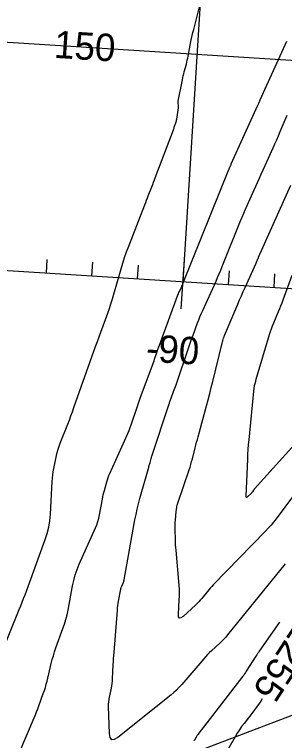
# Model space of a CAD drawing. Extents: x 658976 to 668721, y 639543 to 647196.
# Drawn here: x 661883.9 to 661943.1, y 641733.2 to 641892.5 of the extents above; entities that cross this region are included whole.
import ezdxf

# ---------------------------------------------------------------- set-up
doc = ezdxf.new("R2010")
doc.units = 0
for name, color, linetype in [('Ex_Contour Labels', 7, 'Continuous'), ('Ex_Major Contours', 7, 'Continuous'), ('Ex_Minor Contours', 7, 'Continuous'), ('R_Axis', 7, 'Continuous'), ('R_Axis Annot', 7, 'Continuous'), ('R_Grid', 7, 'Continuous'), ('R_Water', 7, 'Continuous')]:
    doc.layers.add(name, color=color, linetype=linetype)

msp = doc.modelspace()

# ---------------------------------------------------------------- linework, layer by layer
at = {"layer": 'Ex_Major Contours'}
for points in [[(661880.35, 641750.68), (661884.95, 641761.94), (661885.28, 641762.74), (661885.6, 641763.55), (661885.9, 641764.36), (661886.21, 641765.17), (661890.65, 641777.29), (661891.09, 641778.66), (661891.43, 641780.04), (661891.66, 641781.44), (661891.79, 641782.87), (661892.18, 641790.04), (661892.23, 641790.76), (661892.31, 641791.47), (661892.41, 641792.18), (661892.54, 641792.89), (661893.11, 641795.72), (661893.27, 641796.43), (661893.46, 641797.12), (661893.68, 641797.81), (661893.93, 641798.48), (661895.56, 641802.6), (661895.92, 641803.51), (661896.27, 641804.43), (661896.61, 641805.34), (661896.94, 641806.26), (661901.32, 641818.63), (661901.69, 641819.67), (661902.07, 641820.72), (661902.44, 641821.76), (661902.82, 641822.8), (661904.33, 641826.96), (661904.7, 641828), (661905.05, 641829.05), (661905.38, 641830.1), (661905.69, 641831.17), (661907.25, 641836.67), (661907.63, 641837.94), (661908.03, 641839.19), (661908.47, 641840.44), (661908.93, 641841.68), (661912.46, 641850.77), (661912.65, 641851.26), (661912.84, 641851.75), (661913.03, 641852.25), (661913.23, 641852.74), (661914, 641854.71), (661914.19, 641855.2), (661914.38, 641855.69), (661914.57, 641856.19), (661914.76, 641856.68), (661918.72, 641867.2), (661918.79, 641867.39), (661918.86, 641867.58), (661918.93, 641867.78), (661919, 641867.97), (661919.27, 641868.74), (661919.33, 641868.94), (661919.38, 641869.13), (661919.43, 641869.33), (661919.46, 641869.53), (661919.83, 641872.02), (661919.85, 641872.14), (661919.85, 641872.26), (661919.85, 641872.39), (661919.84, 641872.51), (661919.78, 641872.99), (661919.77, 641873.11), (661919.76, 641873.23), (661919.77, 641873.35), (661919.79, 641873.47), (661920.7, 641878.13), (661920.79, 641878.57), (661920.89, 641879.01), (661921, 641879.45), (661921.11, 641879.89), (661921.57, 641881.63), (661921.68, 641882.06), (661921.78, 641882.5), (661921.88, 641882.94), (661921.97, 641883.38), (661922.57, 641886.54), (661922.71, 641887.21), (661922.85, 641887.88), (661923, 641888.55), (661923.17, 641889.22), (661924.65, 641895.06)], [(661938.21, 641742.37), (661937.88, 641741.86), (661937.38, 641741.13), (661936.87, 641740.43), (661936.34, 641739.73), (661934.21, 641736.95), (661933.68, 641736.25), (661933.19, 641735.53), (661932.72, 641734.8), (661932.27, 641734.05), (661929.5, 641729.16)]]:
    msp.add_lwpolyline(points, dxfattribs=at)
at = {"layer": 'Ex_Minor Contours'}
for points in [[(661885.05, 641730.78), (661888.21, 641738.16), (661888.48, 641738.81), (661888.75, 641739.48), (661889.01, 641740.15), (661889.25, 641740.82), (661890.22, 641743.51), (661890.45, 641744.19), (661890.66, 641744.87), (661890.86, 641745.56), (661891.04, 641746.25), (661891.96, 641750.09), (661892.18, 641750.96), (661892.43, 641751.82), (661892.7, 641752.67), (661892.99, 641753.52), (661894.53, 641757.75), (661894.87, 641758.74), (661895.17, 641759.74), (661895.42, 641760.76), (661895.63, 641761.79), (661896.6, 641767.12), (661896.87, 641768.35), (661897.2, 641769.55), (661897.6, 641770.73), (661898.08, 641771.88), (661901.66, 641779.87), (661901.94, 641780.56), (661902.18, 641781.26), (661902.38, 641781.98), (661902.53, 641782.71), (661903.16, 641786.16), (661903.26, 641786.64), (661903.36, 641787.12), (661903.47, 641787.59), (661903.6, 641788.06), (661904.13, 641789.95), (661904.27, 641790.42), (661904.42, 641790.88), (661904.6, 641791.33), (661904.79, 641791.78), (661908.73, 641800.59), (661909, 641801.22), (661909.25, 641801.85), (661909.49, 641802.49), (661909.71, 641803.13), (661910.57, 641805.71), (661910.79, 641806.36), (661911.01, 641807), (661911.24, 641807.65), (661911.47, 641808.29), (661914.35, 641816.15), (661914.49, 641816.53), (661914.62, 641816.91), (661914.76, 641817.29), (661914.89, 641817.67), (661915.41, 641819.2), (661915.54, 641819.58), (661915.67, 641819.96), (661915.8, 641820.34), (661915.94, 641820.72), (661919.64, 641830.75), (661919.73, 641830.99), (661919.83, 641831.23), (661919.93, 641831.47), (661920.04, 641831.71), (661920.47, 641832.66), (661920.57, 641832.9), (661920.68, 641833.14), (661920.78, 641833.38), (661920.88, 641833.62), (661930.87, 641858.48), (661930.92, 641858.58), (661930.96, 641858.69), (661931, 641858.79), (661931.05, 641858.89), (661931.23, 641859.3), (661931.28, 641859.4), (661931.32, 641859.5), (661931.37, 641859.6), (661931.41, 641859.71), (661937.27, 641872.63), (661937.32, 641872.72), (661937.36, 641872.82), (661937.4, 641872.92), (661937.44, 641873.02), (661937.61, 641873.41), (661937.65, 641873.51), (661937.7, 641873.61), (661937.74, 641873.71), (661937.78, 641873.8), (661943.62, 641886.68)], [(661925.38, 641751.14), (661920.58, 641745.51), (661920.02, 641744.88), (661919.43, 641744.28), (661918.81, 641743.71), (661918.17, 641743.17), (661906.57, 641733.9), (661905.78, 641733.41), (661905.2, 641733.39), (661904.84, 641733.84), (661904.7, 641734.76), (661904.53, 641740.67), (661904.53, 641741.19), (661904.56, 641741.7), (661904.62, 641742.2), (661904.71, 641742.71), (661905.14, 641744.72), (661905.24, 641745.23), (661905.32, 641745.74), (661905.37, 641746.25), (661905.41, 641746.76), (661905.54, 641749.8), (661905.58, 641750.48), (661905.62, 641751.15), (661905.66, 641751.83), (661905.71, 641752.51), (661906.45, 641761.79), (661906.5, 641762.3), (661906.56, 641762.8), (661906.63, 641763.3), (661906.71, 641763.79), (661907.19, 641766.41), (661907.23, 641766.59), (661907.28, 641766.76), (661907.34, 641766.93), (661907.4, 641767.1), (661907.7, 641767.76), (661907.77, 641767.93), (661907.83, 641768.1), (661907.88, 641768.27), (661907.91, 641768.45), (661910.31, 641781.6), (661910.54, 641782.79), (661910.8, 641783.97), (661911.08, 641785.15), (661911.4, 641786.33), (661913.31, 641793.18), (661913.33, 641793.26), (661913.36, 641793.34), (661913.38, 641793.42), (661913.41, 641793.51), (661913.52, 641793.83), (661913.55, 641793.92), (661913.57, 641794), (661913.6, 641794.08), (661913.62, 641794.17), (661913.85, 641795.09), (661913.9, 641795.27), (661913.95, 641795.45), (661914.01, 641795.62), (661914.06, 641795.8), (661917.73, 641806.83), (661917.85, 641807.2), (661917.98, 641807.57), (661918.11, 641807.94), (661918.24, 641808.3), (661918.78, 641809.77), (661918.91, 641810.14), (661919.04, 641810.51), (661919.17, 641810.88), (661919.3, 641811.24), (661922.09, 641819.49), (661922.32, 641820.16), (661922.56, 641820.83), (661922.8, 641821.5), (661923.04, 641822.16), (661924.02, 641824.82), (661924.27, 641825.48), (661924.53, 641826.14), (661924.81, 641826.79), (661925.09, 641827.43), (661928.08, 641834.01), (661928.43, 641834.8), (661928.78, 641835.6), (661929.12, 641836.4), (661929.44, 641837.2), (661933.46, 641847.19), (661933.81, 641848.05), (661934.17, 641848.9), (661934.53, 641849.76), (661934.91, 641850.6), (661937.15, 641855.62), (661937.57, 641856.56), (661937.99, 641857.5), (661938.42, 641858.44), (661938.84, 641859.37), (661940.58, 641863.21), (661940.98, 641864.1), (661941.38, 641865), (661941.77, 641865.9), (661942.16, 641866.8), (661943.69, 641870.41)], [(661946.74, 641789.22), (661941.25, 641781.87), (661940.7, 641781.15), (661940.12, 641780.46), (661939.52, 641779.78), (661938.9, 641779.12), (661927.48, 641767.38), (661927.14, 641767.02), (661926.81, 641766.66), (661926.49, 641766.28), (661926.17, 641765.91), (661924.93, 641764.37), (661924.62, 641764), (661924.29, 641763.63), (661923.94, 641763.28), (661923.59, 641762.94), (661920.87, 641760.45), (661920.37, 641760.09), (661920.03, 641760.05), (661919.85, 641760.34), (661919.82, 641760.95), (661920.01, 641764.08), (661920.04, 641764.86), (661920.05, 641765.64), (661920.03, 641766.42), (661919.97, 641767.2), (661919.3, 641774.99), (661919.26, 641775.55), (661919.22, 641776.1), (661919.19, 641776.66), (661919.17, 641777.22), (661919.1, 641779.6), (661919.09, 641780.08), (661919.1, 641780.56), (661919.12, 641781.04), (661919.16, 641781.52), (661919.33, 641783.44), (661919.39, 641783.92), (661919.47, 641784.39), (661919.58, 641784.86), (661919.73, 641785.32), (661922.18, 641792.61), (661922.38, 641793.2), (661922.56, 641793.8), (661922.73, 641794.4), (661922.89, 641795), (661923.51, 641797.43), (661923.66, 641798.03), (661923.82, 641798.64), (661923.98, 641799.24), (661924.15, 641799.84), (661925.99, 641806.64), (661926.35, 641807.97), (661926.69, 641809.31), (661927.03, 641810.65), (661927.37, 641811.99), (661929.42, 641820.42), (661929.45, 641820.56), (661929.49, 641820.7), (661929.53, 641820.84), (661929.57, 641820.98), (661929.73, 641821.53), (661929.78, 641821.66), (661929.82, 641821.8), (661929.87, 641821.93), (661929.93, 641822.07), (661932.83, 641828.94), (661933.22, 641829.86), (661933.62, 641830.77), (661934.02, 641831.69), (661934.43, 641832.6), (661936.85, 641837.92), (661936.88, 641837.98), (661936.91, 641838.05), (661936.93, 641838.11), (661936.96, 641838.18), (661937.29, 641839), (661937.32, 641839.07), (661937.35, 641839.14), (661937.38, 641839.21), (661937.41, 641839.27), (661944.47, 641855.08)], [(661949.43, 641802.73), (661936.52, 641788.4), (661936.46, 641788.33), (661936.4, 641788.25), (661936.34, 641788.18), (661936.28, 641788.1), (661936.05, 641787.8), (661936, 641787.72), (661935.93, 641787.65), (661935.87, 641787.58), (661935.81, 641787.51), (661934.99, 641786.67), (661934.86, 641786.56), (661934.76, 641786.54), (661934.71, 641786.62), (661934.7, 641786.8), (661935.02, 641794.97), (661935.07, 641796.03), (661935.13, 641797.09), (661935.21, 641798.14), (661935.31, 641799.2), (661936.43, 641810.59), (661936.45, 641810.73), (661936.47, 641810.86), (661936.49, 641810.99), (661936.53, 641811.11), (661936.7, 641811.76), (661936.72, 641811.82), (661936.73, 641811.88), (661936.75, 641811.94), (661936.76, 641812.01), (661936.83, 641812.26), (661936.84, 641812.32), (661936.86, 641812.38), (661936.87, 641812.44), (661936.89, 641812.51), (661939.81, 641822.27), (661940.01, 641822.92), (661940.23, 641823.56), (661940.47, 641824.2), (661940.73, 641824.83), (661941.78, 641827.33), (661942.04, 641827.96), (661942.3, 641828.59), (661942.55, 641829.22), (661942.78, 641829.86), (661944.79, 641835.29)], [(661943.24, 641771.97), (661930.61, 641756.39), (661930.21, 641755.91), (661929.8, 641755.46), (661929.36, 641755.02), (661928.92, 641754.59), (661927.09, 641752.92), (661926.64, 641752.49), (661926.21, 641752.05), (661925.78, 641751.6), (661925.38, 641751.14)], [(661941.96, 641759.15), (661937.56, 641752.82), (661937.38, 641752.55), (661937.19, 641752.27), (661937.01, 641752), (661936.83, 641751.72), (661934.7, 641748.39), (661934.52, 641748.12), (661934.33, 641747.85), (661934.14, 641747.58), (661933.94, 641747.32), (661924.09, 641734.55), (661923.98, 641734.4), (661923.88, 641734.25), (661923.78, 641734.1), (661923.69, 641733.95), (661923.33, 641733.32), (661923.24, 641733.16)]]:
    msp.add_lwpolyline(points, dxfattribs=at)
at = {"layer": 'R_Axis'}
for p, q in [((661621.43, 641852.69), (663118.48, 641758.67)), ((661920.46, 641827.9), (661921.22, 641839.87)), ((661890.9, 641835.76), (661891.09, 641838.76)), ((661900.88, 641835.14), (661901.07, 641838.13)), ((661910.86, 641834.51), (661911.05, 641837.51)), ((661930.82, 641833.26), (661931.01, 641836.25)), ((661940.8, 641832.63), (661940.99, 641835.62))]:
    msp.add_line(p, q, dxfattribs=at)
at = {"layer": 'R_Grid'}
for p, q in [((661920.84, 641833.88), (661936.51, 642083.39)), ((661624.56, 641902.59), (663121.61, 641808.57)), ((661621.43, 641852.69), (663118.48, 641758.67))]:
    msp.add_line(p, q, dxfattribs=at)
at = {"layer": 'R_Water'}
msp.add_line((661564.22, 641594.16), (662140.69, 641813.25), dxfattribs=at)

# ---------------------------------------------------------------- texts
at = {"layer": 'Ex_Contour Labels'}
msp.add_text('1255', height=6, rotation=236.9844, dxfattribs=at).set_placement((661945.69, 641759.37))
at = {"layer": 'R_Axis Annot'}
for s, p in [('150', (661892.46, 641883)), ('-90', (661912.62, 641816.37))]:
    msp.add_text(s, height=6, rotation=356.4063, dxfattribs=at).set_placement(p)

doc.saveas('drawing.dxf')
